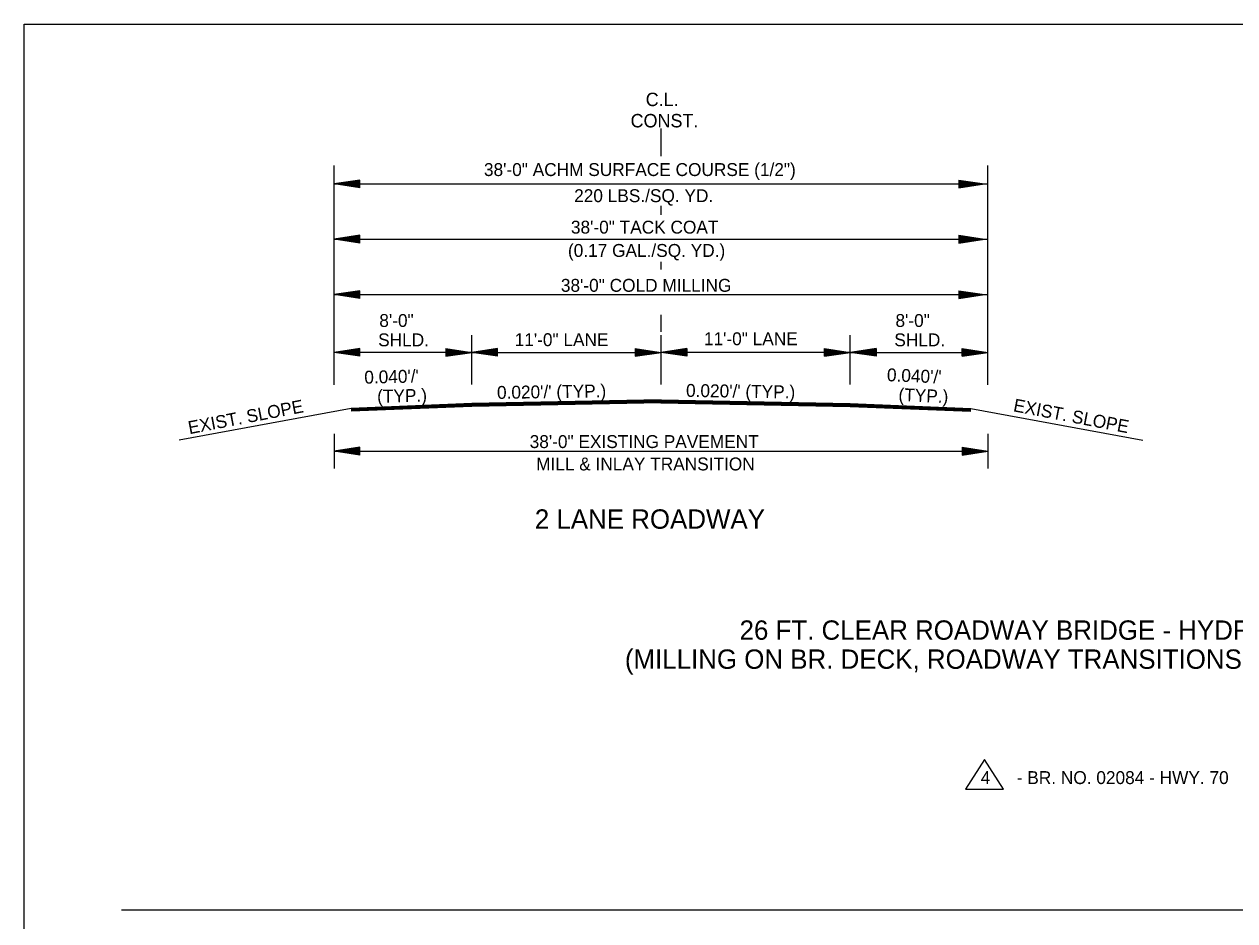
# Model space of a CAD drawing. Extents: x 544199 to 1930787, y -1968972 to 596640.
# Drawn here: x 544199 to 544903, y -1950425 to -1949903 of the extents above; entities that cross this region are included whole.
import ezdxf

# ---------------------------------------------------------------- set-up
doc = ezdxf.new("R2010")
doc.units = 0
for name, color, linetype in [('R_Border', 7, 'Continuous'), ('R_Draft', 7, 'Continuous'), ('R_No Plot', 7, 'Continuous')]:
    doc.layers.add(name, color=color, linetype=linetype)

msp = doc.modelspace()

# ---------------------------------------------------------------- linework, layer by layer
at = {"layer": 'R_Border'}
for p, q in [((544459.05, -1950123.95), (544389.05, -1950126.75)), ((544459.05, -1950124.25), (544389.05, -1950127.05)), ((544459.05, -1950124.55), (544389.05, -1950127.35)), ((544459.05, -1950124.85), (544389.05, -1950127.65)), ((544459.05, -1950125.15), (544389.05, -1950127.95)), ((544459.05, -1950125.45), (544389.05, -1950128.25)), ((544459.05, -1950125.62), (544389.05, -1950128.42)), ((544679.05, -1950123.95), (544749.05, -1950126.75)), ((544679.05, -1950124.25), (544749.05, -1950127.05)), ((544679.05, -1950124.55), (544749.05, -1950127.35)), ((544679.05, -1950124.85), (544749.05, -1950127.65)), ((544679.05, -1950125.15), (544749.05, -1950127.95)), ((544679.05, -1950125.45), (544749.05, -1950128.25)), ((544679.05, -1950125.62), (544749.05, -1950128.42)), ((544757.01, -1950330.86), (544745.97, -1950348.16)), ((544768.05, -1950348.16), (544757.01, -1950330.86)), ((544745.97, -1950348.16), (544768.05, -1950348.16)), ((544255.57, -1950418.19), (545283.52, -1950418.19))]:
    msp.add_line(p, q, dxfattribs=at)
at = {"layer": 'R_Draft'}
for p, q in [((544569.05, -1949980.17), (544569.05, -1949964.1)), ((544379.05, -1950112.97), (544379.05, -1949985.49)), ((544759.05, -1950112.97), (544759.05, -1949985.49)), ((544394.05, -1949993.97), (544379.05, -1949996.22)), ((544379.05, -1949996.22), (544759.05, -1949996.22)), ((544394.05, -1949998.47), (544379.05, -1949996.22)), ((544394.05, -1949994.35), (544381.55, -1949996.22)), ((544394.05, -1949998.1), (544381.55, -1949996.22)), ((544394.05, -1949994.73), (544384.13, -1949996.22)), ((544394.05, -1949997.71), (544384.13, -1949996.22)), ((544394.05, -1949995.1), (544386.63, -1949996.22)), ((544394.05, -1949997.34), (544386.63, -1949996.22)), ((544394.05, -1949995.49), (544389.17, -1949996.22)), ((544394.05, -1949996.95), (544389.17, -1949996.22)), ((544394.05, -1949995.87), (544391.68, -1949996.22)), ((544394.05, -1949996.57), (544391.68, -1949996.22)), ((544394.05, -1949998.47), (544394.05, -1949993.97)), ((544742.05, -1949993.97), (544757.05, -1949996.22)), ((544742.05, -1949993.97), (544742.05, -1949998.47)), ((544742.05, -1949994.35), (544754.54, -1949996.22)), ((544742.05, -1949994.73), (544751.96, -1949996.22)), ((544742.05, -1949995.1), (544749.46, -1949996.22)), ((544742.05, -1949995.49), (544746.92, -1949996.22)), ((544742.05, -1949995.87), (544744.42, -1949996.22)), ((544742.05, -1949998.47), (544757.05, -1949996.22)), ((544742.05, -1949996.96), (544746.92, -1949996.22)), ((544742.05, -1949997.71), (544751.96, -1949996.22)), ((544742.05, -1949998.1), (544754.54, -1949996.22)), ((544742.05, -1949997.34), (544749.46, -1949996.22)), ((544742.05, -1949996.57), (544744.42, -1949996.22)), ((544569.05, -1950014.11), (544569.05, -1950009.07)), ((544394.05, -1950026.12), (544379.05, -1950028.37)), ((544379.05, -1950028.37), (544759.05, -1950028.37)), ((544394.05, -1950030.62), (544379.05, -1950028.37)), ((544394.05, -1950026.49), (544381.55, -1950028.37)), ((544394.05, -1950030.24), (544381.55, -1950028.37)), ((544394.05, -1950026.88), (544384.13, -1950028.37)), ((544394.05, -1950029.86), (544384.13, -1950028.37)), ((544394.05, -1950027.25), (544386.63, -1950028.37)), ((544394.05, -1950029.49), (544386.63, -1950028.37)), ((544394.05, -1950027.63), (544389.17, -1950028.37)), ((544394.05, -1950029.1), (544389.17, -1950028.37)), ((544394.05, -1950028.02), (544391.68, -1950028.37)), ((544394.05, -1950028.72), (544391.68, -1950028.37)), ((544394.05, -1950030.62), (544394.05, -1950026.12)), ((544742.05, -1950026.12), (544757.05, -1950028.37)), ((544742.05, -1950026.12), (544742.05, -1950030.62)), ((544742.05, -1950026.49), (544754.54, -1950028.37)), ((544742.05, -1950026.88), (544751.96, -1950028.37)), ((544742.05, -1950027.25), (544749.46, -1950028.37)), ((544742.05, -1950027.64), (544746.92, -1950028.37)), ((544742.05, -1950028.02), (544744.42, -1950028.37)), ((544742.05, -1950030.62), (544757.05, -1950028.37)), ((544742.05, -1950029.1), (544746.92, -1950028.37)), ((544742.05, -1950029.86), (544751.96, -1950028.37)), ((544742.05, -1950030.24), (544754.54, -1950028.37)), ((544742.05, -1950029.49), (544749.46, -1950028.37)), ((544742.05, -1950028.72), (544744.42, -1950028.37)), ((544569.05, -1950045.96), (544569.05, -1950041.5)), ((544394.05, -1950058.36), (544379.05, -1950060.61)), ((544394.05, -1950058.73), (544381.55, -1950060.61)), ((544394.05, -1950059.12), (544384.13, -1950060.61)), ((544394.05, -1950059.49), (544386.63, -1950060.61)), ((544394.05, -1950059.87), (544389.17, -1950060.61)), ((544394.05, -1950060.26), (544391.68, -1950060.61)), ((544394.05, -1950062.86), (544394.05, -1950058.36)), ((544742.05, -1950058.36), (544757.05, -1950060.61)), ((544742.05, -1950058.36), (544742.05, -1950062.86)), ((544742.05, -1950058.73), (544754.54, -1950060.61)), ((544742.05, -1950059.12), (544751.96, -1950060.61)), ((544742.05, -1950059.49), (544749.46, -1950060.61)), ((544742.05, -1950059.88), (544746.92, -1950060.61)), ((544742.05, -1950060.26), (544744.42, -1950060.61)), ((544379.05, -1950060.61), (544759.05, -1950060.61)), ((544394.05, -1950062.86), (544379.05, -1950060.61)), ((544394.05, -1950062.48), (544381.55, -1950060.61)), ((544394.05, -1950062.1), (544384.13, -1950060.61)), ((544394.05, -1950061.73), (544386.63, -1950060.61)), ((544394.05, -1950061.34), (544389.17, -1950060.61)), ((544394.05, -1950060.96), (544391.68, -1950060.61)), ((544742.05, -1950062.86), (544757.05, -1950060.61)), ((544742.05, -1950061.34), (544746.92, -1950060.61)), ((544742.05, -1950062.1), (544751.96, -1950060.61)), ((544742.05, -1950062.48), (544754.54, -1950060.61)), ((544742.05, -1950061.73), (544749.46, -1950060.61)), ((544742.05, -1950060.96), (544744.42, -1950060.61)), ((544569.05, -1950074.14), (544569.05, -1950072.26)), ((544569.05, -1950082.13), (544569.05, -1950074.14)), ((544459.05, -1950112.8), (544459.05, -1950084.25)), ((544569.05, -1950112.8), (544569.05, -1950084.25)), ((544679.05, -1950112.8), (544679.05, -1950084.25)), ((544394.05, -1950091.89), (544379.05, -1950094.14)), ((544459.05, -1950094.14), (544379.05, -1950094.14)), ((544394.05, -1950096.39), (544379.05, -1950094.14)), ((544394.05, -1950092.27), (544381.55, -1950094.14)), ((544394.05, -1950096.02), (544381.55, -1950094.14)), ((544394.05, -1950092.65), (544384.13, -1950094.14)), ((544394.05, -1950095.64), (544384.13, -1950094.14)), ((544394.05, -1950093.03), (544386.63, -1950094.14)), ((544394.05, -1950095.26), (544386.63, -1950094.14)), ((544394.05, -1950093.41), (544389.17, -1950094.14)), ((544394.05, -1950094.87), (544389.17, -1950094.14)), ((544394.05, -1950093.79), (544391.68, -1950094.14)), ((544394.05, -1950094.5), (544391.68, -1950094.14)), ((544394.05, -1950096.39), (544394.05, -1950091.89)), ((544444.05, -1950091.89), (544459.05, -1950094.14)), ((544444.05, -1950091.89), (544444.05, -1950096.39)), ((544444.05, -1950092.27), (544456.54, -1950094.14)), ((544444.05, -1950092.65), (544453.96, -1950094.14)), ((544444.05, -1950093.03), (544451.46, -1950094.14)), ((544444.05, -1950093.42), (544448.92, -1950094.14)), ((544444.05, -1950093.79), (544446.42, -1950094.14)), ((544444.05, -1950096.39), (544459.05, -1950094.14)), ((544444.05, -1950094.88), (544448.92, -1950094.14)), ((544444.05, -1950095.64), (544453.96, -1950094.14)), ((544444.05, -1950096.02), (544456.54, -1950094.14)), ((544444.05, -1950095.26), (544451.46, -1950094.14)), ((544444.05, -1950094.5), (544446.42, -1950094.14)), ((544474.05, -1950091.89), (544459.05, -1950094.14)), ((544474.05, -1950096.39), (544459.05, -1950094.14)), ((544459.05, -1950094.14), (544569.05, -1950094.14)), ((544474.05, -1950092.27), (544461.55, -1950094.14)), ((544474.05, -1950096.02), (544461.55, -1950094.14)), ((544474.05, -1950092.65), (544464.13, -1950094.14)), ((544474.05, -1950095.64), (544464.13, -1950094.14)), ((544474.05, -1950093.03), (544466.63, -1950094.14)), ((544474.05, -1950095.26), (544466.63, -1950094.14)), ((544474.05, -1950093.41), (544469.17, -1950094.14)), ((544474.05, -1950094.87), (544469.17, -1950094.14)), ((544474.05, -1950093.79), (544471.68, -1950094.14)), ((544474.05, -1950094.5), (544471.68, -1950094.14)), ((544474.05, -1950096.39), (544474.05, -1950091.89)), ((544554.05, -1950091.89), (544569.05, -1950094.14)), ((544554.05, -1950091.89), (544554.05, -1950096.39)), ((544554.05, -1950092.27), (544566.54, -1950094.14)), ((544554.05, -1950092.65), (544563.96, -1950094.14)), ((544554.05, -1950093.03), (544561.46, -1950094.14)), ((544554.05, -1950093.42), (544558.92, -1950094.14)), ((544554.05, -1950093.79), (544556.42, -1950094.14)), ((544554.05, -1950096.39), (544569.05, -1950094.14)), ((544554.05, -1950094.88), (544558.92, -1950094.14)), ((544554.05, -1950095.64), (544563.96, -1950094.14)), ((544554.05, -1950096.02), (544566.54, -1950094.14)), ((544554.05, -1950095.26), (544561.46, -1950094.14)), ((544554.05, -1950094.5), (544556.42, -1950094.14)), ((544584.05, -1950091.89), (544569.05, -1950094.14)), ((544679.05, -1950094.14), (544569.05, -1950094.14)), ((544584.05, -1950096.39), (544569.05, -1950094.14)), ((544584.05, -1950092.27), (544571.55, -1950094.14)), ((544584.05, -1950096.02), (544571.55, -1950094.14)), ((544584.05, -1950092.65), (544574.13, -1950094.14)), ((544584.05, -1950095.64), (544574.13, -1950094.14)), ((544584.05, -1950093.03), (544576.63, -1950094.14)), ((544584.05, -1950095.26), (544576.63, -1950094.14)), ((544584.05, -1950093.42), (544579.17, -1950094.14)), ((544584.05, -1950094.88), (544579.17, -1950094.14)), ((544584.05, -1950093.79), (544581.68, -1950094.14)), ((544584.05, -1950094.5), (544581.68, -1950094.14)), ((544584.05, -1950091.89), (544584.05, -1950096.39)), ((544664.05, -1950091.89), (544679.05, -1950094.14)), ((544664.05, -1950096.39), (544664.05, -1950091.89)), ((544664.05, -1950092.27), (544676.54, -1950094.14)), ((544664.05, -1950092.65), (544673.96, -1950094.14)), ((544664.05, -1950093.03), (544671.46, -1950094.14)), ((544664.05, -1950093.41), (544668.92, -1950094.14)), ((544664.05, -1950093.79), (544666.42, -1950094.14)), ((544664.05, -1950096.39), (544679.05, -1950094.14)), ((544664.05, -1950094.87), (544668.92, -1950094.14)), ((544664.05, -1950095.64), (544673.96, -1950094.14)), ((544664.05, -1950096.02), (544676.54, -1950094.14)), ((544664.05, -1950095.26), (544671.46, -1950094.14)), ((544664.05, -1950094.5), (544666.42, -1950094.14)), ((544694.05, -1950091.89), (544679.05, -1950094.14)), ((544694.05, -1950096.39), (544679.05, -1950094.14)), ((544679.05, -1950094.14), (544759.05, -1950094.14)), ((544694.05, -1950092.27), (544681.55, -1950094.14)), ((544694.05, -1950096.02), (544681.55, -1950094.14)), ((544694.05, -1950092.65), (544684.13, -1950094.14)), ((544694.05, -1950095.64), (544684.13, -1950094.14)), ((544694.05, -1950093.03), (544686.63, -1950094.14)), ((544694.05, -1950095.26), (544686.63, -1950094.14)), ((544694.05, -1950093.42), (544689.17, -1950094.14)), ((544694.05, -1950094.88), (544689.17, -1950094.14)), ((544694.05, -1950093.79), (544691.68, -1950094.14)), ((544694.05, -1950094.5), (544691.68, -1950094.14)), ((544694.05, -1950091.89), (544694.05, -1950096.39)), ((544744.05, -1950091.89), (544759.05, -1950094.14)), ((544744.05, -1950096.39), (544744.05, -1950091.89)), ((544744.05, -1950092.27), (544756.54, -1950094.14)), ((544744.05, -1950092.65), (544753.96, -1950094.14)), ((544744.05, -1950093.03), (544751.46, -1950094.14)), ((544744.05, -1950093.41), (544748.92, -1950094.14)), ((544744.05, -1950093.79), (544746.42, -1950094.14)), ((544744.05, -1950096.39), (544759.05, -1950094.14)), ((544744.05, -1950094.87), (544748.92, -1950094.14)), ((544744.05, -1950095.64), (544753.96, -1950094.14)), ((544744.05, -1950096.02), (544756.54, -1950094.14)), ((544744.05, -1950095.26), (544751.46, -1950094.14)), ((544744.05, -1950094.5), (544746.42, -1950094.14)), ((544569.05, -1950121.75), (544459.05, -1950123.95)), ((544569.04, -1950122.05), (544459.05, -1950124.25)), ((544569.05, -1950122.35), (544459.05, -1950124.55)), ((544569.07, -1950122.65), (544459.05, -1950124.85)), ((544569.07, -1950122.95), (544459.05, -1950125.15)), ((544569.08, -1950123.25), (544459.05, -1950125.45)), ((544569.08, -1950123.42), (544459.05, -1950125.62)), ((544569.01, -1950123.42), (544679.05, -1950125.62)), ((544569.02, -1950122.95), (544679.05, -1950125.15)), ((544569.02, -1950123.25), (544679.05, -1950125.45)), ((544569.03, -1950122.65), (544679.05, -1950124.85)), ((544569.04, -1950122.05), (544679.05, -1950124.25)), ((544569.04, -1950122.35), (544679.05, -1950124.55)), ((544569.05, -1950121.75), (544679.05, -1950123.95)), ((544389.05, -1950126.75), (544288.98, -1950145.13)), ((544749.05, -1950126.75), (544849.12, -1950145.13)), ((544379.05, -1950141.61), (544379.05, -1950161.61)), ((544759.05, -1950141.61), (544759.05, -1950161.61)), ((544394.05, -1950149.36), (544379.05, -1950151.61)), ((544379.05, -1950151.61), (544759.05, -1950151.61)), ((544394.05, -1950153.86), (544379.05, -1950151.61)), ((544394.05, -1950149.73), (544381.55, -1950151.61)), ((544394.05, -1950153.48), (544381.55, -1950151.61)), ((544394.05, -1950150.12), (544384.13, -1950151.61)), ((544394.05, -1950153.1), (544384.13, -1950151.61)), ((544394.05, -1950150.49), (544386.63, -1950151.61)), ((544394.05, -1950152.73), (544386.63, -1950151.61)), ((544394.05, -1950150.87), (544389.17, -1950151.61)), ((544394.05, -1950152.34), (544389.17, -1950151.61)), ((544394.05, -1950151.26), (544391.68, -1950151.61)), ((544394.05, -1950151.96), (544391.68, -1950151.61)), ((544394.05, -1950153.86), (544394.05, -1950149.36)), ((544744.05, -1950149.36), (544759.05, -1950151.61)), ((544744.05, -1950149.36), (544744.05, -1950153.86)), ((544744.05, -1950149.73), (544756.54, -1950151.61)), ((544744.05, -1950150.12), (544753.96, -1950151.61)), ((544744.05, -1950150.49), (544751.46, -1950151.61)), ((544744.05, -1950150.88), (544748.92, -1950151.61)), ((544744.05, -1950151.26), (544746.42, -1950151.61)), ((544744.05, -1950153.86), (544759.05, -1950151.61)), ((544744.05, -1950152.34), (544748.92, -1950151.61)), ((544744.05, -1950153.1), (544753.96, -1950151.61)), ((544744.05, -1950153.48), (544756.54, -1950151.61)), ((544744.05, -1950152.73), (544751.46, -1950151.61)), ((544744.05, -1950151.96), (544746.42, -1950151.61))]:
    msp.add_line(p, q, dxfattribs=at)
at = {"layer": 'R_No Plot'}
msp.add_lwpolyline([(544198.93, -1950431.01), (544198.93, -1949903.39), (545382.98, -1949903.39), (545382.98, -1949952.79), (545560.58, -1949952.79), (545560.58, -1949970.64), (545578.78, -1949970.64), (545578.78, -1949967.39), (545656.45, -1949967.39)], dxfattribs=at)

# ---------------------------------------------------------------- texts
at = {"layer": 'R_Draft'}
for s, height, p in [('C.L.', 7.8, (544560.15, -1949951.01)), ('CONST.', 7.8, (544551.37, -1949963.37)), ('38\'-0" ACHM SURFACE COURSE (1/2")', 7.5, (544466.14, -1949991.65)), ('220 LBS./SQ. YD. ', 7.5, (544518.56, -1950006.83)), ('38\'-0" TACK COAT', 7.5, (544516.69, -1950025.12)), ('(0.17 GAL./SQ. YD.)', 7.5, (544514.96, -1950038.66)), ('38\'-0" COLD MILLING', 7.5, (544510.85, -1950058.94)), ('8\'-0"', 7.5, (544405.32, -1950079.39)), ('8\'-0"', 7.5, (544705.32, -1950079.39)), ('SHLD.', 7.5, (544404.64, -1950090.64)), ('11\'-0" LANE', 7.5, (544483.99, -1950090.54)), ('11\'-0" LANE', 7.5, (544593.99, -1950090.01)), ('SHLD.', 7.5, (544704.64, -1950090.64)), ('38\'-0" EXISTING PAVEMENT', 7.5, (544492.72, -1950149.78)), ('MILL & INLAY TRANSITION', 7.5, (544496.44, -1950162.78)), ('2 LANE ROADWAY', 11.25, (544495.71, -1950196.68)), ('26 FT. CLEAR ROADWAY BRIDGE - HYDRODEMOLITION', 11.25, (544614.71, -1950261.23)), ('(MILLING ON BR. DECK, ROADWAY TRANSITIONS, AND NEW GUARDRAIL)', 11.25, (544548.05, -1950278.11)), ('4', 7.5, (544754.88, -1950345.11)), ('- BR. NO. 02084 - HWY. 70', 7.5, (544775.81, -1950345.11))]:
    msp.add_text(s, height=height, dxfattribs=at).set_placement(p)
for s, rotation, p in [("0.040'/' ", 1.31838, (544396.67, -1950112.38)), ("0.040'/' ", 357.64559, (544700.23, -1950110.89)), ('(TYP.)', 1.31838, (544404.14, -1950123.46)), ("0.020'/' (TYP.)", 0.87191, (544473.77, -1950121.23)), ("0.020'/' (TYP.)", 359.12809, (544583.54, -1950120)), ('(TYP.)', 357.64559, (544706.96, -1950122.43)), ('EXIST. SLOPE', 10.88286, (544294.96, -1950141.75)), ('EXIST. SLOPE', 349.11714, (544773.43, -1950128.35))]:
    msp.add_text(s, height=7.5, rotation=rotation, dxfattribs=at).set_placement(p)

doc.saveas('drawing.dxf')
